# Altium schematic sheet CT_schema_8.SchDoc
size 308 x 210 mm
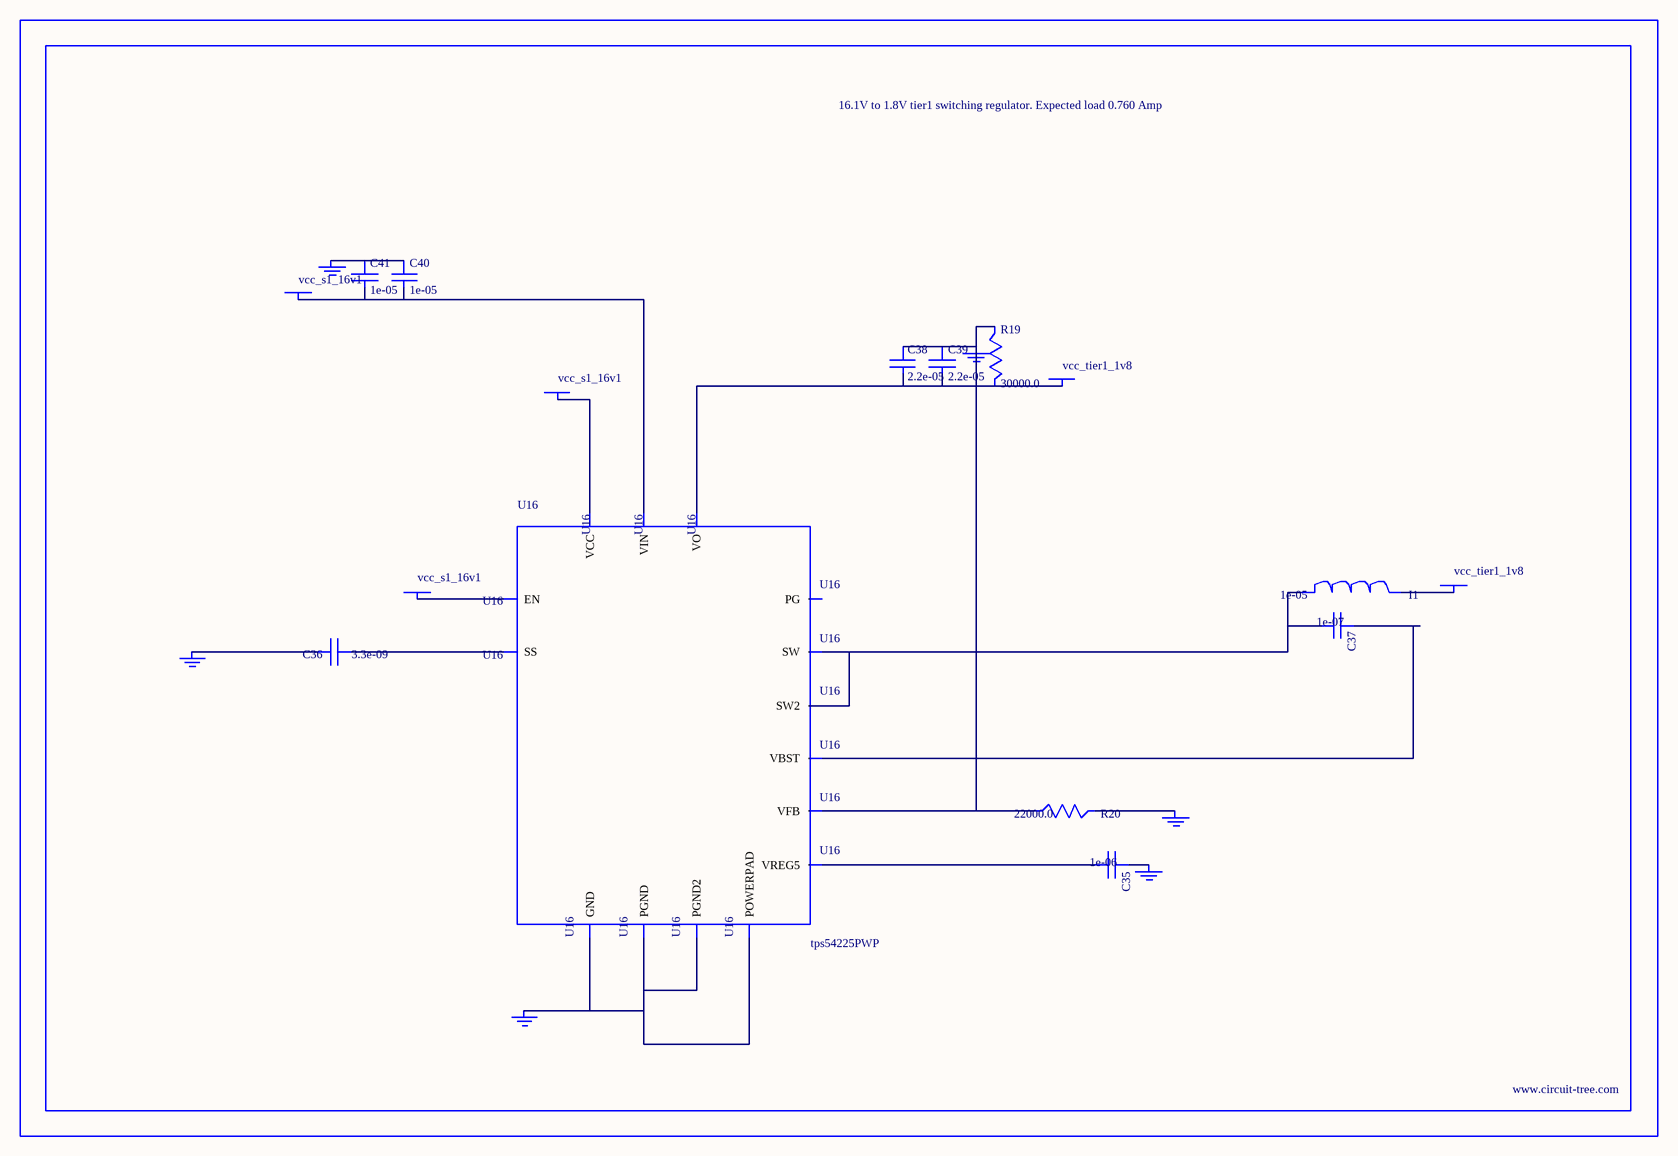
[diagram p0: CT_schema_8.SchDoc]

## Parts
BORDER7  (no value)
C35  1e-06  [C0603]
C36  3.3e-09  [C0402]
C37  1e-07  [C0402]
C38  2.2e-05  [C1210]
C39  2.2e-05  [C1210]
C40  1e-05  [C1206]
C41  1e-05  [C1206]
GND_INSTANCE_7_0  (no value)
GND_INSTANCE_7_1  (no value)
GND_INSTANCE_7_2  (no value)
GND_INSTANCE_7_3  (no value)
GND_INSTANCE_7_4  (no value)
GND_INSTANCE_7_5  (no value)
I1  1e-05  [IND_PM3316]
POWER_INSTANCE_7_0  vcc_tier1_1v8
POWER_INSTANCE_7_1  vcc_s1_16v1
POWER_INSTANCE_7_2  vcc_tier1_1v8
POWER_INSTANCE_7_3  vcc_s1_16v1
POWER_INSTANCE_7_4  vcc_s1_16v1
R19  30000.0  [R0603]
R20  22000.0  [R0603]
U16  tps54225PWP  [HTSSOP14]

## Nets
NetC35_1: C35.1 GND_INSTANCE_7_2.0(GND)
NetC35_2: C35.2 U16.3(VREG5)
NetC36_1: C36.1 U16.4(SS)
NetC36_2: C36.2 GND_INSTANCE_7_3.0(GND)
NetC37_1: C37.1 U16.12(VBST)
NetC37_2: C37.2 I1.1 U16.10(SW) U16.11(SW2)
NetC38_1: C38.1 C39.1 GND_INSTANCE_7_0.0(GND) R19.1 R20.1 U16.2(VFB)
NetC38_2: C38.2 C39.2 POWER_INSTANCE_7_0.0(PWR) R19.2 U16.1(VO)
NetC40_1: C40.1 C41.1 GND_INSTANCE_7_5.0(GND)
NetC40_2: C40.2 C41.2 POWER_INSTANCE_7_3.0(PWR) U16.13(VIN)
NetGND_INSTANCE_7_1_0: GND_INSTANCE_7_1.0(GND) R20.2
NetGND_INSTANCE_7_4_0: GND_INSTANCE_7_4.0(GND) U16.5(GND) U16.8(PGND) U16.9(PGND2) U16.15(POWERPAD)
NetI1_2: I1.2 POWER_INSTANCE_7_2.0(PWR)
NetPOWER_INSTANCE_7_1_0: POWER_INSTANCE_7_1.0(PWR) U16.7(EN)
NetPOWER_INSTANCE_7_4_0: POWER_INSTANCE_7_4.0(PWR) U16.14(VCC)

Not connected (* = marked no-connect by the designer): U16 6(PG)

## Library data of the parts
BORDER7 = BORDER_PAGE7
C35 = C0603C105K3RACTU
C36 = C0402C332K3RAC
C37 = C0402C104K3RACTU
C38 C39 = GRM32ER61E226ME15L
C40 C41 = C1206C106K3RACTU
GND_INSTANCE_7_0-GND_INSTANCE_7_5 = GND
I1 = PM3316-100M-RC
POWER_INSTANCE_7_0-POWER_INSTANCE_7_4 = PWR
R19 = RC0603JR-0730KL
R20 = RC0603JR-0722KL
